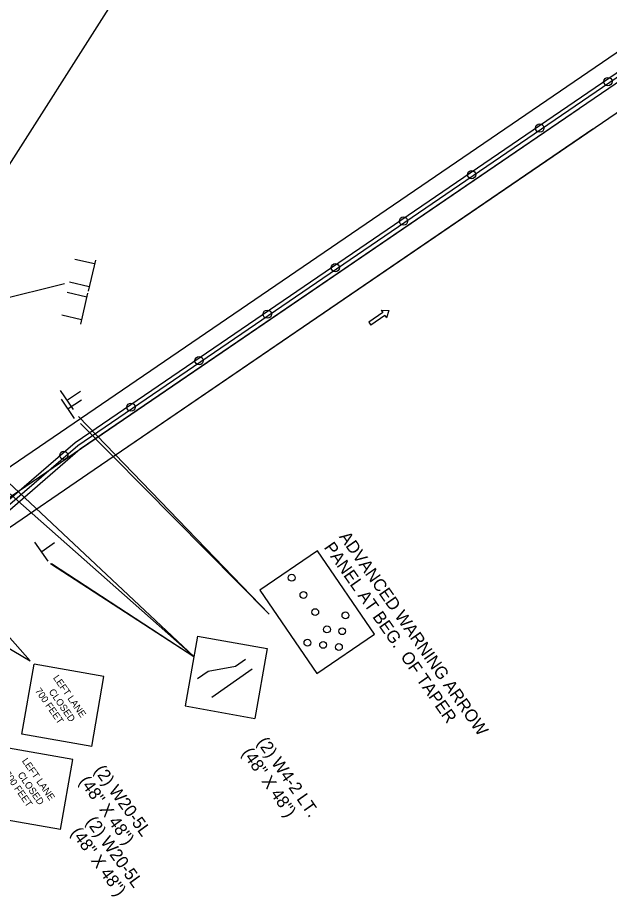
# Model space of a CAD drawing. Extents: x 659657 to 668193, y 633084 to 648639.
# Drawn here: x 662115.3 to 662402.2, y 641437.9 to 641864.1 of the extents above; entities that cross this region are included whole.
import ezdxf

# ---------------------------------------------------------------- set-up
doc = ezdxf.new("R2010")
doc.units = 0
for name, color, linetype in [('R_Draft', 7, 'Continuous'), ('R_MOT_Stage 1C', 7, 'Continuous'), ('R_MOT_Stage 1C_Striping', 7, 'Continuous'), ('R_MOT_Stage 1C_Striping_PPM', 7, 'Continuous'), ('R_MOT_Stage 2_Striping_PPM', 7, 'Continuous'), ('R_MOT_Stage 3_Striping_PPM', 7, 'Continuous'), ('R_MOT_Stage 4_Striping_PPM', 7, 'Continuous'), ('R_MOT_Stage 5_Striping_PPM', 7, 'Continuous'), ('R_ROW Annot', 7, 'Continuous'), ('S_EXISTING_ALIGNMENT', 7, 'Continuous'), ('T_Notes', 7, 'Continuous'), ('T_SIGNAL CONTROL CABINET', 7, 'Continuous'), ('TEMP_SIGNAL_HEAD_STAGE 2', 7, 'Continuous')]:
    doc.layers.add(name, color=color, linetype=linetype)

msp = doc.modelspace()

# ---------------------------------------------------------------- linework, layer by layer
at = {"layer": 'R_Draft'}
for p, q in [((662142.87, 641669.73), (662136.52, 641679.02)), ((662139.85, 641674.45), (662146.19, 641678.78)), ((662145.78, 641667.31), (662237.22, 641574.78)), ((662200.7, 641554.26), (662104.7, 641639.1)), ((662130.02, 641600.45), (662123.58, 641609.67)), ((662126.95, 641605.13), (662133.24, 641609.53)), ((662131.26, 641599.37), (662200.7, 641554.26)), ((662202.46, 641564.14), (662196.45, 641530.27)), ((662202.46, 641564.14), (662236.32, 641558.13)), ((662236.32, 641558.13), (662230.31, 641524.26)), ((662220.97, 641549.55), (662225.8, 641552.93)), ((662207.59, 641547.12), (662220.97, 641549.55)), ((662209.43, 641534.58), (662229.05, 641548.28)), ((662202.51, 641543.58), (662207.59, 641547.12)), ((662196.45, 641530.27), (662230.31, 641524.26)), ((662142.04, 641504.27), (662108.18, 641510.21)), ((662136.13, 641470.4), (662142.04, 641504.27)), ((662136.13, 641470.4), (662102.25, 641476.33))]:
    msp.add_line(p, q, dxfattribs=at)
msp.add_lwpolyline([(662288.3, 641565.1), (662260.67, 641605.56), (662232.68, 641586.45), (662260.31, 641545.99)], close=True, dxfattribs=at)
for centre in [(662248.18, 641592.45), (662253.88, 641584.11), (662259.57, 641575.76), (662274.22, 641574.18), (662265.27, 641567.41), (662272.63, 641566.51), (662255.79, 641560.94), (662263.41, 641559.88), (662271.04, 641558.83)]:
    msp.add_circle(centre, 1.66, dxfattribs=at)
at = {"layer": 'R_MOT_Stage 1C'}
for p, q in [((662143.21, 641658.04), (662495.6, 641898.67)), ((662496.72, 641897.01), (662144.43, 641656.46)), ((662029.22, 641559.88), (662143.21, 641658.04)), ((662144.43, 641656.46), (662030.5, 641558.35))]:
    msp.add_line(p, q, dxfattribs=at)
for centre in [(662401.48, 641833.04), (662368.44, 641810.48), (662335.41, 641787.92), (662302.38, 641765.37), (662269.34, 641742.81), (662236.31, 641720.25), (662203.27, 641697.7), (662170.24, 641675.14), (662137.68, 641651.8)]:
    msp.add_circle(centre, 2, dxfattribs=at)
at = {"layer": 'R_MOT_Stage 1C_Striping'}
for p, q in [((662145.65, 641654.87), (662497.85, 641895.36)), ((662031.78, 641556.81), (662145.65, 641654.87))]:
    msp.add_line(p, q, dxfattribs=at)
at = {"layer": 'R_MOT_Stage 1C_Striping_PPM'}
msp.add_line((662152.42, 641644.96), (662504.62, 641885.45), dxfattribs=at)
at = {"layer": 'R_MOT_Stage 2_Striping_PPM'}
for p, q in [((662474.17, 641893.72), (662094.31, 641634.34)), ((662098.77, 641622.86), (662387.46, 641819.98)), ((662152.42, 641644.96), (662394.23, 641810.07)), ((662105.54, 641612.95), (662152.42, 641644.96))]:
    msp.add_line(p, q, dxfattribs=at)
at = {"layer": 'R_MOT_Stage 3_Striping_PPM'}
for p, q in [((662474.17, 641893.72), (662094.31, 641634.34)), ((662098.77, 641622.86), (662387.46, 641819.98)), ((662152.42, 641644.96), (662394.23, 641810.07)), ((662105.54, 641612.95), (662152.42, 641644.96))]:
    msp.add_line(p, q, dxfattribs=at)
at = {"layer": 'R_MOT_Stage 4_Striping_PPM'}
for p, q in [((662474.17, 641893.72), (662094.31, 641634.34)), ((662098.77, 641622.86), (662387.46, 641819.98)), ((662152.42, 641644.96), (662394.23, 641810.07)), ((662105.54, 641612.95), (662152.42, 641644.96))]:
    msp.add_line(p, q, dxfattribs=at)
at = {"layer": 'R_MOT_Stage 5_Striping_PPM'}
for p, q in [((662474.17, 641893.72), (662094.31, 641634.34)), ((662152.42, 641644.96), (662504.62, 641885.45)), ((662098.77, 641622.86), (662387.46, 641819.98)), ((662105.54, 641612.95), (662152.42, 641644.96))]:
    msp.add_line(p, q, dxfattribs=at)
at = {"layer": 'R_ROW Annot'}
for p, q in [((662142.44, 641673.95), (662136.1, 641683.24)), ((662139.42, 641678.66), (662145.76, 641682.99)), ((662144.79, 641670.67), (662237.22, 641574.78)), ((662200.7, 641554.26), (662105.37, 641643.71)), ((662121.4, 641552.11), (662064.31, 641616.24)), ((662130.02, 641600.45), (662123.58, 641609.67)), ((662126.95, 641605.13), (662133.24, 641609.53)), ((662131.7, 641599.41), (662200.7, 641554.26)), ((662091.17, 641570.06), (662121.4, 641552.11)), ((662202.46, 641564.14), (662196.45, 641530.27)), ((662202.46, 641564.14), (662236.32, 641558.13)), ((662236.32, 641558.13), (662230.31, 641524.26)), ((662220.97, 641549.55), (662225.8, 641552.93)), ((662117.36, 641516.59), (662123.28, 641550.47)), ((662157.15, 641544.53), (662123.28, 641550.47)), ((662207.59, 641547.12), (662220.97, 641549.55)), ((662209.43, 641534.58), (662229.05, 641548.28)), ((662151.23, 641510.66), (662157.15, 641544.53)), ((662202.51, 641543.58), (662207.59, 641547.12)), ((662196.45, 641530.27), (662230.31, 641524.26)), ((662151.23, 641510.66), (662117.36, 641516.59))]:
    msp.add_line(p, q, dxfattribs=at)
msp.add_lwpolyline([(662288.3, 641565.1), (662260.67, 641605.56), (662232.68, 641586.45), (662260.31, 641545.99)], close=True, dxfattribs=at)
for centre in [(662248.18, 641592.45), (662253.88, 641584.11), (662259.57, 641575.76), (662274.22, 641574.18), (662265.27, 641567.41), (662272.63, 641566.51), (662255.79, 641560.94), (662263.41, 641559.88), (662271.04, 641558.83)]:
    msp.add_circle(centre, 1.66, dxfattribs=at)
at = {"layer": 'S_EXISTING_ALIGNMENT'}
msp.add_line((662006.37, 641627.8), (662163.94, 641875.56), dxfattribs=at)
at = {"layer": 'T_Notes'}
for p, q in [((662142.44, 641673.95), (662136.1, 641683.24)), ((662139.42, 641678.66), (662145.76, 641682.99)), ((662144.79, 641670.67), (662237.22, 641574.78)), ((662200.7, 641554.26), (662105.37, 641643.71)), ((662121.4, 641552.11), (662064.31, 641616.24)), ((662130.02, 641600.45), (662123.58, 641609.67)), ((662126.95, 641605.13), (662133.24, 641609.53)), ((662131.7, 641599.41), (662200.7, 641554.26)), ((662091.17, 641570.06), (662121.4, 641552.11)), ((662202.46, 641564.14), (662196.45, 641530.27)), ((662202.46, 641564.14), (662236.32, 641558.13)), ((662236.32, 641558.13), (662230.31, 641524.26)), ((662220.97, 641549.55), (662225.8, 641552.93)), ((662117.36, 641516.59), (662123.28, 641550.47)), ((662157.15, 641544.53), (662123.28, 641550.47)), ((662207.59, 641547.12), (662220.97, 641549.55)), ((662209.43, 641534.58), (662229.05, 641548.28)), ((662151.23, 641510.66), (662157.15, 641544.53)), ((662202.51, 641543.58), (662207.59, 641547.12)), ((662196.45, 641530.27), (662230.31, 641524.26)), ((662151.23, 641510.66), (662117.36, 641516.59))]:
    msp.add_line(p, q, dxfattribs=at)
msp.add_lwpolyline([(662288.3, 641565.1), (662260.67, 641605.56), (662232.68, 641586.45), (662260.31, 641545.99)], close=True, dxfattribs=at)
for centre in [(662248.18, 641592.45), (662253.88, 641584.11), (662259.57, 641575.76), (662274.22, 641574.18), (662265.27, 641567.41), (662272.63, 641566.51), (662255.79, 641560.94), (662263.41, 641559.88), (662271.04, 641558.83)]:
    msp.add_circle(centre, 1.66, dxfattribs=at)
at = {"layer": 'T_SIGNAL CONTROL CABINET'}
for p, q in [((662292.37, 641721.05), (662285.53, 641716.39)), ((662293.32, 641719.66), (662286.49, 641714.99)), ((662291.57, 641722.22), (662292.37, 641721.05)), ((662291.57, 641722.22), (662295.26, 641722)), ((662293.32, 641719.66), (662294.11, 641718.5)), ((662295.26, 641722), (662294.11, 641718.5)), ((662285.53, 641716.39), (662286.49, 641714.99))]:
    msp.add_line(p, q, dxfattribs=at)
at = {"layer": 'TEMP_SIGNAL_HEAD_STAGE 2'}
for p, q in [((662152.55, 641744.6), (662143.06, 641746.82)), ((662153, 641746.5), (662149.47, 641731.45)), ((662149.95, 641733.5), (662140.46, 641735.73)), ((662065.54, 641717.22), (662138.03, 641735.13)), ((662148.79, 641728.57), (662139.3, 641730.8)), ((662149.24, 641730.48), (662145.71, 641715.42)), ((662146.19, 641717.48), (662136.7, 641719.7))]:
    msp.add_line(p, q, dxfattribs=at)

# ---------------------------------------------------------------- texts
at = {"layer": 'R_Draft'}
for s, height, rotation, p in [('ADVANCED WARNING ARROW', 6, 305.0175, (662270.94, 641612.29)), ('PANEL AT BEG.  OF TAPER', 6, 305.0175, (662263.56, 641607.12)), ('(2) W4-2 LT.', 6, 304.9379, (662231.12, 641512.63)), ('(48" X 48")', 6, 304.9379, (662223.74, 641507.48)), ('LEFT LANE', 3.339, 305.0714, (662117.21, 641503.57)), ('700 FEET', 3.339, 305.0705, (662108.48, 641497.33)), ('CLOSED', 3.339, 305.0713, (662115.11, 641496.89)), ('(2) W20-5L', 6, 305.8666, (662148.13, 641474.12)), ('(48" X 48")', 6, 305.8666, (662140.84, 641468.84))]:
    msp.add_text(s, height=height, rotation=rotation, dxfattribs=at).set_placement(p)
at = {"layer": 'R_ROW Annot'}
for s, height, rotation, p in [('ADVANCED WARNING ARROW', 6, 305.0175, (662270.94, 641612.29)), ('PANEL AT BEG.  OF TAPER', 6, 305.0175, (662263.56, 641607.12)), ('LEFT LANE', 3.339, 305.0714, (662132.31, 641543.83)), ('700 FEET', 3.339, 305.0705, (662123.58, 641537.59)), ('CLOSED', 3.339, 305.0713, (662130.21, 641537.15)), ('(2) W4-2 LT.', 6, 304.9379, (662231.12, 641512.63)), ('(48" X 48")', 6, 304.9379, (662223.74, 641507.48)), ('(2) W20-5L', 6, 305.8666, (662152.12, 641498.96)), ('(48" X 48")', 6, 305.8666, (662144.82, 641493.69))]:
    msp.add_text(s, height=height, rotation=rotation, dxfattribs=at).set_placement(p)
at = {"layer": 'T_Notes'}
for s, height, rotation, p in [('ADVANCED WARNING ARROW', 6, 305.0175, (662270.94, 641612.29)), ('PANEL AT BEG.  OF TAPER', 6, 305.0175, (662263.56, 641607.12)), ('LEFT LANE', 3.339, 305.0714, (662132.31, 641543.83)), ('700 FEET', 3.339, 305.0705, (662123.58, 641537.59)), ('CLOSED', 3.339, 305.0713, (662130.21, 641537.15)), ('(2) W4-2 LT.', 6, 304.9379, (662231.12, 641512.63)), ('(48" X 48")', 6, 304.9379, (662223.74, 641507.48)), ('(2) W20-5L', 6, 305.8666, (662152.12, 641498.96)), ('(48" X 48")', 6, 305.8666, (662144.82, 641493.69))]:
    msp.add_text(s, height=height, rotation=rotation, dxfattribs=at).set_placement(p)

doc.saveas('drawing.dxf')
